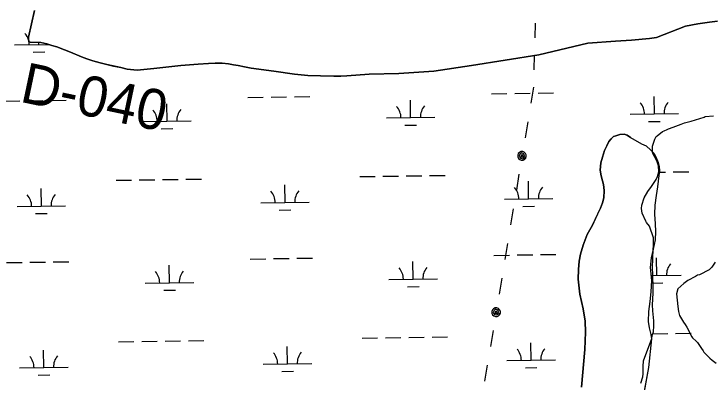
# Model space of a CAD drawing. Extents: x 3807117 to 3845308, y 337856 to 363736.
# Drawn here: x 3834429 to 3835869, y 344010 to 344768 of the extents above; entities that cross this region are included whole.
import ezdxf

# ---------------------------------------------------------------- set-up
doc = ezdxf.new("R2010")
doc.units = 0
for name, color, linetype in [('V-RIVR-RANG-IDEN', 7, 'Continuous'), ('V-SITE-VEGE', 7, 'Continuous'), ('V-TOPO-SHOR', 7, 'Continuous'), ('V-UTIL-LINE', 7, 'Continuous'), ('V-WETL-SWMP', 7, 'Continuous')]:
    doc.layers.add(name, color=color, linetype=linetype)

msp = doc.modelspace()

# ---------------------------------------------------------------- linework, layer by layer
at = {"layer": 'V-SITE-VEGE'}
for p, q in [((3835823.4, 344547.7), (3835850.1, 344556.1)), ((3835850.1, 344556.1), (3835852.4, 344557)), ((3835852.4, 344557), (3835869.9, 344558.4)), ((3835786.6, 344535.2), (3835792.1, 344537.5)), ((3835792.1, 344537.5), (3835803.1, 344541.2)), ((3835803.1, 344541.2), (3835810, 344544)), ((3835810, 344544), (3835823.4, 344547.7)), ((3835753.4, 344517.6), (3835764.4, 344526)), ((3835764.4, 344526), (3835768.1, 344527.8)), ((3835768.1, 344527.8), (3835774.1, 344530.6)), ((3835774.1, 344530.6), (3835776.9, 344531.5)), ((3835776.9, 344531.5), (3835786.6, 344535.2)), ((3835744.2, 344496), (3835748.8, 344510.7)), ((3835748.8, 344510.7), (3835751.6, 344515.8)), ((3835751.6, 344515.8), (3835753.4, 344517.6)), ((3835743.8, 344490.9), (3835744.2, 344496)), ((3835744.2, 344484), (3835743.8, 344490.9)), ((3835745.6, 344479.4), (3835744.2, 344484)), ((3835751.2, 344468.8), (3835745.6, 344479.4)), ((3835753.5, 344463.7), (3835751.2, 344468.8)), ((3835756.3, 344455.9), (3835753.5, 344463.7)), ((3835757.2, 344443), (3835756.3, 344455.9)), ((3835754.4, 344433.8), (3835757.2, 344443)), ((3835741.6, 344413), (3835751.2, 344427.3)), ((3835751.2, 344427.3), (3835754.4, 344433.8)), ((3835734.2, 344402.4), (3835741.6, 344413)), ((3835726.9, 344389.5), (3835734.2, 344402.4)), ((3835721.8, 344374.3), (3835726.9, 344389.5)), ((3835721.4, 344367.8), (3835721.8, 344374.3)), ((3835722.3, 344358.1), (3835721.4, 344367.8)), ((3835730.2, 344341.5), (3835722.3, 344358.1)), ((3835731.5, 344339.2), (3835730.2, 344341.5)), ((3835737.5, 344331.4), (3835731.5, 344339.2)), ((3835746.3, 344307), (3835737.5, 344331.4)), ((3835745.9, 344292.7), (3835746.3, 344307)), ((3835744.6, 344268.7), (3835745.9, 344292.7)), ((3835744.6, 344260.4), (3835744.6, 344268.7)), ((3835743.7, 344247.1), (3835744.1, 344249.8)), ((3835744.1, 344249.8), (3835744.6, 344260.4)), ((3835872.7, 344257.4), (3835866.3, 344246.8)), ((3835744.6, 344230.5), (3835743.7, 344247.1)), ((3835860.3, 344241.3), (3835840.9, 344231.1)), ((3835866.3, 344246.8), (3835860.3, 344241.3)), ((3835744.6, 344220.3), (3835744.6, 344230.5)), ((3835745.1, 344214.4), (3835744.6, 344220.3)), ((3835832.7, 344227.9), (3835816.5, 344219.5)), ((3835834.5, 344229.2), (3835832.7, 344227.9)), ((3835836.3, 344230.2), (3835834.5, 344229.2)), ((3835840.9, 344231.1), (3835836.3, 344230.2)), ((3835745.1, 344206.5), (3835745.1, 344214.4)), ((3835745.6, 344201.5), (3835745.1, 344206.5)), ((3835808.2, 344213.1), (3835796.3, 344202)), ((3835811, 344215.4), (3835808.2, 344213.1)), ((3835816.5, 344219.5), (3835811, 344215.4)), ((3835743.8, 344169.6), (3835745.6, 344193.6)), ((3835745.6, 344193.6), (3835745.6, 344201.5)), ((3835796.3, 344202), (3835793.1, 344191.8)), ((3835793.1, 344191.8), (3835796.3, 344165.6)), ((3835744.7, 344156.7), (3835743.8, 344169.6)), ((3835796.3, 344165.6), (3835797.7, 344155.9)), ((3835746.6, 344136.5), (3835744.7, 344156.7)), ((3835797.7, 344155.9), (3835799.6, 344147.6)), ((3835746.6, 344125.9), (3835746.6, 344136.5)), ((3835799.6, 344147.6), (3835807.9, 344133.8)), ((3835745.7, 344113.4), (3835746.6, 344125.9)), ((3835807.9, 344133.8), (3835811.1, 344128.7)), ((3835811.1, 344128.7), (3835814.8, 344123.2)), ((3835814.8, 344123.2), (3835825, 344103.4)), ((3835742.5, 344100.1), (3835743.4, 344106)), ((3835743.4, 344106), (3835745.7, 344113.4)), ((3835725.5, 344053.9), (3835742.5, 344100.1)), ((3835825, 344103.4), (3835826.4, 344101.1)), ((3835826.4, 344101.1), (3835833.8, 344094.2)), ((3835833.8, 344094.2), (3835836.5, 344091.4)), ((3835836.5, 344091.4), (3835844.9, 344079.5)), ((3835844.9, 344079.5), (3835848.6, 344074.4)), ((3835848.6, 344074.4), (3835849.9, 344072.1)), ((3835849.9, 344072.1), (3835861.9, 344059.2)), ((3835724.6, 344042.4), (3835725.5, 344053.9)), ((3835861.9, 344059.2), (3835866.6, 344055.1)), ((3835866.6, 344055.1), (3835875.3, 344049.1)), ((3835724.6, 344027.2), (3835724.6, 344042.4)), ((3835720.1, 344008.3), (3835723.7, 344020.7)), ((3835723.7, 344020.7), (3835724.6, 344027.2))]:
    msp.add_line(p, q, dxfattribs=at)
at = {"layer": 'V-TOPO-SHOR'}
for points in [[(3834471.1, 344775.7), (3834458.9, 344720.9), (3834458.5, 344714.8), (3834460.3, 344710.8), (3834462.3, 344710.2), (3834474.1, 344710.1), (3834484, 344709.9), (3834496.6, 344706.7), (3834506.7, 344703.6), (3834516.8, 344700.7), (3834532.7, 344694.8), (3834545.4, 344689.6), (3834567.7, 344680.2), (3834578.7, 344675.9), (3834591, 344672.2), (3834606.2, 344667.8), (3834620.2, 344664.3), (3834633.8, 344661.2), (3834648.8, 344657.8), (3834662.2, 344654.7), (3834682.3, 344652.8), (3834716.5, 344656.2), (3834772.5, 344662), (3834808, 344665.2), (3834829.1, 344666.2), (3834843.1, 344667.2), (3834857.7, 344666.8), (3834870.3, 344665.5), (3834880.6, 344663.5), (3834890.4, 344662), (3834903.5, 344659.6), (3834917.5, 344656.9), (3834963.7, 344650.8), (3835006.7, 344644.6), (3835034.1, 344641.7), (3835059.9, 344641.3), (3835087.8, 344640), (3835102, 344640), (3835114.4, 344641), (3835160.5, 344644.4), (3835221.5, 344645.5), (3835293.3, 344650.7), (3835371, 344662.5), (3835509.7, 344684.2), (3835610.8, 344708), (3835667.8, 344712.7), (3835700.4, 344714.5), (3835737.6, 344717.7), (3835752, 344720.1)], [(3835752, 344720.1), (3835811.8, 344743.3), (3835837.6, 344748.4), (3835861.1, 344751.6), (3835877.9, 344753.6)], [(3835698.4, 344513.9), (3835691.5, 344519), (3835685.8, 344520.8), (3835676.7, 344520), (3835668.6, 344517.6), (3835663.9, 344516), (3835658.6, 344511.3), (3835654, 344505.8), (3835649.7, 344497.1), (3835645, 344487), (3835641.1, 344473.6), (3835637.7, 344461.7), (3835636, 344446.9), (3835638.3, 344435.1), (3835641.1, 344425), (3835643.1, 344416.9), (3835644.5, 344404.5), (3835643.7, 344389.9), (3835640.8, 344379.2), (3835636.5, 344368.1), (3835629.6, 344353.5), (3835620.1, 344333.6), (3835609.5, 344314.4), (3835600.9, 344292.5), (3835595.4, 344273.5), (3835592.8, 344259.1), (3835591.7, 344242.1), (3835591.1, 344222.2), (3835594.5, 344191.6), (3835600.9, 344161.4), (3835604.9, 344135.7), (3835605.9, 344112.8), (3835604.5, 344077.5), (3835598, 343999.5)], [(3835698.4, 344513.9), (3835721.6, 344501), (3835730.9, 344496.8), (3835740.6, 344488.2), (3835746.5, 344481.7), (3835750.7, 344474.4), (3835755.6, 344462.8), (3835757.6, 344454.1), (3835758.4, 344445.8), (3835757.2, 344435.8), (3835755.9, 344423.9), (3835753.9, 344412.1), (3835751.4, 344394.3), (3835749, 344374.8), (3835748.3, 344356.3), (3835749.5, 344335.8), (3835750.1, 344320.6), (3835749.5, 344303.5), (3835745.2, 344284.1), (3835740.9, 344266.2), (3835738.8, 344246.1), (3835741.8, 344219.6), (3835740.6, 344196), (3835738.5, 344175.9), (3835735.4, 344155.4), (3835735, 344135), (3835737, 344121.6), (3835740.6, 344108.2), (3835741.6, 344099.2), (3835735.8, 344040.2), (3835703.7, 343865.5)]]:
    msp.add_lwpolyline(points, dxfattribs=at)
at = {"layer": 'V-UTIL-LINE'}
for points in [[(3835502.3, 344749.2), (3835501.4, 344719)], [(3835500.5, 344683.4), (3835499.6, 344653.2)], [(3835498.7, 344617.7), (3835493.2, 344584.9)], [(3835486.8, 344546.4), (3835481.4, 344513.6)], [(3835475.2, 344476), (3835477.8, 344477.2), (3835475.7, 344478.4), (3835473.3, 344477.1), (3835473.1, 344474.2), (3835476.5, 344473.5), (3835480.3, 344476.1), (3835479.2, 344480.3), (3835474.8, 344482.3), (3835470.9, 344479.8), (3835469.3, 344475.7), (3835471.7, 344471.5), (3835477.1, 344470.3), (3835484, 344474.5), (3835483.9, 344478), (3835482.5, 344481.2), (3835479.9, 344483.6), (3835476.6, 344484.9), (3835473.1, 344484.8), (3835469.9, 344483.3), (3835467.5, 344480.8), (3835466.3, 344477.5), (3835466.4, 344474), (3835467.8, 344470.8), (3835470.4, 344468.4), (3835473.7, 344467.1), (3835477.2, 344467.2), (3835480.4, 344468.7), (3835482.8, 344471.2), (3835484, 344474.5)], [(3835468.9, 344438.4), (3835463.5, 344405.6)], [(3835457.1, 344367.1), (3835451.6, 344334.3)], [(3835445.2, 344295.8), (3835439.8, 344263)], [(3835433.4, 344224.4), (3835428, 344191.6)], [(3835421.7, 344154.1), (3835424.3, 344155.3), (3835422.3, 344156.4), (3835419.9, 344155.2), (3835419.7, 344152.3), (3835423, 344151.6), (3835426.9, 344154.2), (3835425.8, 344158.3), (3835421.4, 344160.4), (3835417.5, 344157.9), (3835415.8, 344153.7), (3835418.3, 344149.6), (3835423.6, 344148.4), (3835430.6, 344152.6), (3835430.5, 344156.1), (3835429.1, 344159.3), (3835426.5, 344161.7), (3835423.2, 344162.9), (3835419.7, 344162.8), (3835416.5, 344161.4), (3835414.1, 344158.8), (3835412.9, 344155.5), (3835413, 344152), (3835414.4, 344148.8), (3835417, 344146.4), (3835420.3, 344145.2), (3835423.8, 344145.3), (3835427, 344146.7), (3835429.4, 344149.3), (3835430.6, 344152.6)], [(3835415.5, 344116.5), (3835410.1, 344083.7)], [(3835403.7, 344045.1), (3835398.2, 344012.4)]]:
    msp.add_lwpolyline(points, dxfattribs=at)
at = {"layer": 'V-WETL-SWMP'}
for p, q in [((3834458.9, 344720.9), (3834471.1, 344775.7)), ((3835877.9, 344753.6), (3835861.1, 344751.6)), ((3835811.8, 344743.3), (3835752, 344720.1)), ((3835837.6, 344748.4), (3835811.8, 344743.3)), ((3835861.1, 344751.6), (3835837.6, 344748.4)), ((3834458.5, 344714.8), (3834458.9, 344720.9)), ((3834460.3, 344710.8), (3834458.5, 344714.8)), ((3834462.3, 344710.2), (3834460.3, 344710.8)), ((3834484, 344709.9), (3834462.3, 344710.2)), ((3834480.1, 344705.4), (3834480.1, 344709.9)), ((3834496.6, 344706.7), (3834484, 344709.9)), ((3835667.8, 344712.7), (3835610.8, 344708)), ((3835700.4, 344714.5), (3835667.8, 344712.7)), ((3835737.6, 344717.7), (3835700.4, 344714.5)), ((3835752, 344720.1), (3835737.6, 344717.7)), ((3834430.1, 344704.6), (3834500.1, 344705.7)), ((3834506.7, 344703.6), (3834496.6, 344706.7)), ((3834516.8, 344700.7), (3834506.7, 344703.6)), ((3834532.7, 344694.8), (3834516.8, 344700.7)), ((3835610.8, 344708), (3835509.7, 344684.2)), ((3834468.4, 344689.7), (3834492.4, 344690.1)), ((3834545.4, 344689.6), (3834532.7, 344694.8)), ((3834567.7, 344680.2), (3834545.4, 344689.6)), ((3835509.7, 344684.2), (3835371, 344662.5)), ((3834578.7, 344675.9), (3834567.7, 344680.2)), ((3834591, 344672.2), (3834578.7, 344675.9)), ((3834606.2, 344667.8), (3834591, 344672.2)), ((3834620.2, 344664.3), (3834606.2, 344667.8)), ((3834843.1, 344667.2), (3834829.1, 344666.2)), ((3834857.7, 344666.8), (3834843.1, 344667.2)), ((3834870.3, 344665.5), (3834857.7, 344666.8)), ((3834648.8, 344657.8), (3834620.2, 344664.3)), ((3834662.2, 344654.7), (3834648.8, 344657.8)), ((3834682.3, 344652.8), (3834662.2, 344654.7)), ((3834716.5, 344656.2), (3834682.3, 344652.8)), ((3834772.5, 344662), (3834716.5, 344656.2)), ((3834808, 344665.2), (3834772.5, 344662)), ((3834829.1, 344666.2), (3834808, 344665.2)), ((3834880.6, 344663.5), (3834870.3, 344665.5)), ((3834890.4, 344662), (3834880.6, 344663.5)), ((3834903.5, 344659.6), (3834890.4, 344662)), ((3834917.5, 344656.9), (3834903.5, 344659.6)), ((3834963.7, 344650.8), (3834917.5, 344656.9)), ((3835371, 344662.5), (3835293.3, 344650.7)), ((3835006.7, 344644.6), (3834963.7, 344650.8)), ((3835034.1, 344641.7), (3835006.7, 344644.6)), ((3835059.9, 344641.3), (3835034.1, 344641.7)), ((3835087.8, 344640), (3835059.9, 344641.3)), ((3835102, 344640), (3835087.8, 344640)), ((3835114.4, 344641), (3835102, 344640)), ((3835160.5, 344644.4), (3835114.4, 344641)), ((3835221.5, 344645.5), (3835160.5, 344644.4)), ((3835293.3, 344650.7), (3835221.5, 344645.5)), ((3834910.3, 344596.4), (3834942.3, 344596.8)), ((3834958.3, 344597.1), (3834990.3, 344597.6)), ((3835006.3, 344597.8), (3835038.3, 344598.3)), ((3835412.2, 344603.9), (3835444.2, 344604.4)), ((3835460.2, 344604.6), (3835492.2, 344605.1)), ((3835508.2, 344605.3), (3835540.2, 344605.8)), ((3835747.7, 344562.5), (3835747.1, 344598.5)), ((3834408.5, 344588.8), (3834440.5, 344589.3)), ((3834456.5, 344589.6), (3834488.5, 344590)), ((3834504.5, 344590.3), (3834536.5, 344590.8)), ((3834744, 344547.4), (3834743.4, 344583.4)), ((3835245.8, 344555), (3835245.3, 344590.9)), ((3835195.8, 344554.2), (3835295.8, 344555.7)), ((3835697.7, 344561.7), (3835797.7, 344563.2)), ((3834694, 344546.7), (3834794, 344548.2)), ((3835234.1, 344539.3), (3835258.1, 344539.7)), ((3835735.9, 344546.9), (3835759.9, 344547.2)), ((3834732.2, 344531.8), (3834756.2, 344532.2)), ((3835654, 344505.8), (3835658.6, 344511.3)), ((3835658.6, 344511.3), (3835663.9, 344516)), ((3835663.9, 344516), (3835668.6, 344517.6)), ((3835668.6, 344517.6), (3835676.7, 344520)), ((3835676.7, 344520), (3835685.8, 344520.8)), ((3835685.8, 344520.8), (3835691.5, 344519)), ((3835691.5, 344519), (3835698.4, 344513.9)), ((3835698.4, 344513.9), (3835721.6, 344501)), ((3835645, 344487), (3835649.7, 344497.1)), ((3835649.7, 344497.1), (3835654, 344505.8)), ((3835721.6, 344501), (3835730.9, 344496.8)), ((3835730.9, 344496.8), (3835740.6, 344488.2)), ((3835641.1, 344473.6), (3835645, 344487)), ((3835740.6, 344488.2), (3835746.5, 344481.7)), ((3835746.5, 344481.7), (3835750.7, 344474.4)), ((3835637.7, 344461.7), (3835641.1, 344473.6)), ((3835750.7, 344474.4), (3835755.6, 344462.8)), ((3835636, 344446.9), (3835637.7, 344461.7)), ((3835755.6, 344462.8), (3835757.6, 344454.1)), ((3835757.6, 344454.1), (3835758.4, 344445.8)), ((3835638.3, 344435.1), (3835636, 344446.9)), ((3835758.4, 344445.8), (3835755.9, 344423.9)), ((3835758, 344442.5), (3835770.6, 344442.7)), ((3835786.6, 344443), (3835818.6, 344443.4)), ((3834638.9, 344425.8), (3834670.9, 344426.3)), ((3834686.9, 344426.5), (3834718.9, 344427)), ((3834734.9, 344427.2), (3834766.9, 344427.7)), ((3834782.9, 344427.9), (3834814.9, 344428.4)), ((3835140.8, 344433.3), (3835172.8, 344433.8)), ((3835188.8, 344434), (3835220.8, 344434.5)), ((3835236.8, 344434.7), (3835268.8, 344435.2)), ((3835284.8, 344435.4), (3835316.8, 344435.9)), ((3835488.8, 344387.8), (3835488.3, 344423.8)), ((3835641.1, 344425), (3835638.3, 344435.1)), ((3835643.1, 344416.9), (3835641.1, 344425)), ((3835755.9, 344423.9), (3835753.9, 344412.1)), ((3834485.1, 344372.7), (3834484.6, 344408.7)), ((3834987, 344380.2), (3834986.4, 344416.2)), ((3835644.5, 344404.5), (3835643.1, 344416.9)), ((3835753.9, 344412.1), (3835751.4, 344394.3)), ((3835643.7, 344389.9), (3835644.5, 344404.5)), ((3835751.4, 344394.3), (3835749, 344374.8)), ((3834937, 344379.5), (3835037, 344381)), ((3835438.8, 344387), (3835538.8, 344388.5)), ((3835636.5, 344368.1), (3835640.8, 344379.2)), ((3835640.8, 344379.2), (3835643.7, 344389.9)), ((3834435.1, 344372), (3834535.1, 344373.5)), ((3834975.2, 344364.6), (3834999.2, 344365)), ((3835477.1, 344372.1), (3835501.1, 344372.5)), ((3835620.1, 344333.6), (3835636.5, 344368.1)), ((3835749, 344374.8), (3835748.3, 344356.3)), ((3834473.4, 344357.1), (3834497.4, 344357.5)), ((3835748.3, 344356.3), (3835749.5, 344335.8)), ((3835749.5, 344335.8), (3835750.1, 344320.6)), ((3835609.5, 344314.4), (3835620.1, 344333.6)), ((3835600.9, 344292.5), (3835609.5, 344314.4)), ((3835750.1, 344320.6), (3835749.5, 344303.5)), ((3835595.4, 344273.5), (3835600.9, 344292.5)), ((3835749.5, 344303.5), (3835745.2, 344284.1)), ((3835745.2, 344284.1), (3835740.9, 344266.2)), ((3834915.3, 344263.7), (3834947.3, 344264.2)), ((3834963.3, 344264.4), (3834995.3, 344264.9)), ((3835011.3, 344265.2), (3835043.3, 344265.6)), ((3835417.2, 344271.2), (3835449.2, 344271.7)), ((3835465.1, 344272), (3835497.1, 344272.4)), ((3835513.1, 344272.7), (3835545.1, 344273.2)), ((3835592.8, 344259.1), (3835595.4, 344273.5)), ((3835740.9, 344266.2), (3835738.8, 344246.1)), ((3835752.7, 344229.8), (3835752.1, 344265.8)), ((3834413.5, 344256.2), (3834445.4, 344256.7)), ((3834461.4, 344256.9), (3834493.4, 344257.4)), ((3834509.4, 344257.6), (3834541.4, 344258.1)), ((3834749, 344214.8), (3834748.4, 344250.8)), ((3835250.8, 344222.3), (3835250.3, 344258.3)), ((3835591.7, 344242.1), (3835592.8, 344259.1)), ((3835591.1, 344222.2), (3835591.7, 344242.1)), ((3835738.8, 344246.1), (3835741.8, 344219.6)), ((3835200.8, 344221.6), (3835300.8, 344223.1)), ((3835594.5, 344191.6), (3835591.1, 344222.2)), ((3835740.7, 344229.7), (3835802.7, 344230.6)), ((3834699, 344214), (3834798.9, 344215.5)), ((3835239, 344206.7), (3835263, 344207.1)), ((3835741.8, 344219.6), (3835740.6, 344196)), ((3835741.5, 344214.2), (3835764.9, 344214.6)), ((3834737.2, 344199.2), (3834761.2, 344199.5)), ((3835600.9, 344161.4), (3835594.5, 344191.6)), ((3835740.6, 344196), (3835738.5, 344175.9)), ((3835738.5, 344175.9), (3835735.4, 344155.4)), ((3835604.9, 344135.7), (3835600.9, 344161.4)), ((3835735.4, 344155.4), (3835735, 344135)), ((3835605.9, 344112.8), (3835604.9, 344135.7)), ((3835735, 344135), (3835737, 344121.6)), ((3835737, 344121.6), (3835740.6, 344108.2)), ((3835604.5, 344077.5), (3835605.9, 344112.8)), ((3835740.6, 344108.2), (3835741.6, 344099.2)), ((3835743.6, 344109.6), (3835775.6, 344110.1)), ((3835791.6, 344110.3), (3835823.6, 344110.8)), ((3834643.9, 344093.1), (3834675.9, 344093.6)), ((3834691.9, 344093.9), (3834723.9, 344094.3)), ((3834739.9, 344094.6), (3834771.9, 344095.1)), ((3834787.9, 344095.3), (3834819.9, 344095.8)), ((3835145.8, 344100.7), (3835177.8, 344101.1)), ((3835193.8, 344101.4), (3835225.8, 344101.9)), ((3835241.8, 344102.1), (3835273.8, 344102.6)), ((3835289.8, 344102.8), (3835321.8, 344103.3)), ((3835493.8, 344055.1), (3835493.3, 344091.1)), ((3835741.6, 344099.2), (3835735.8, 344040.2)), ((3834992, 344047.6), (3834991.4, 344083.6)), ((3835598, 343999.5), (3835604.5, 344077.5)), ((3834490.1, 344040.1), (3834489.6, 344076.1)), ((3834942, 344046.9), (3835042, 344048.4)), ((3835443.8, 344054.4), (3835543.8, 344055.9)), ((3834440.1, 344039.3), (3834540.1, 344040.8)), ((3835482, 344039.5), (3835506, 344039.9)), ((3835735.8, 344040.2), (3835703.7, 343865.5)), ((3834478.3, 344024.5), (3834502.3, 344024.8)), ((3834980.2, 344032), (3835004.2, 344032.4))]:
    msp.add_line(p, q, dxfattribs=at)
for centre, start, end in [((3834424.9, 344705), 17.1363, 41.6302), ((3834424.9, 344705), 0.0865, 13.996), ((3835692.4, 344562.1), 0.0865, 41.6302), ((3835802.9, 344563.8), 140.0865, 181.6302), ((3834688.7, 344547.1), 0.0865, 41.6302), ((3834799.2, 344548.7), 140.0865, 181.6302), ((3835190.6, 344554.6), 0.0865, 41.6302), ((3835301.1, 344556.3), 140.0865, 181.6302), ((3835433.6, 344387.4), 0.0865, 41.6302), ((3835544.1, 344389.1), 140.0865, 181.6302), ((3834429.9, 344372.4), 0.0865, 41.6302), ((3834540.4, 344374), 140.0865, 181.6302), ((3834931.7, 344379.9), 0.0865, 41.6302), ((3835042.2, 344381.5), 140.0865, 181.6302), ((3835807.9, 344231.1), 140.0865, 181.6302), ((3834693.7, 344214.4), 0.0865, 41.6302), ((3834804.2, 344216.1), 140.0865, 181.6302), ((3835195.6, 344222), 0.0865, 41.6302), ((3835306, 344223.6), 140.0865, 181.6302), ((3835438.6, 344054.8), 0.0865, 41.6302), ((3835549, 344056.4), 140.0865, 181.6302), ((3834434.9, 344039.7), 0.0865, 41.6302), ((3834545.3, 344041.4), 140.0865, 181.6302), ((3834936.7, 344047.2), 0.0865, 41.6302), ((3835047.2, 344048.9), 140.0865, 181.6302)]:
    msp.add_arc(centre, 35.2, start, end, dxfattribs=at)

# ---------------------------------------------------------------- texts
at = {"layer": 'V-RIVR-RANG-IDEN'}
msp.add_text('D-040', height=83, rotation=348.1113, dxfattribs=at).set_placement((3834438.5, 344588.1))

doc.saveas('drawing.dxf')
